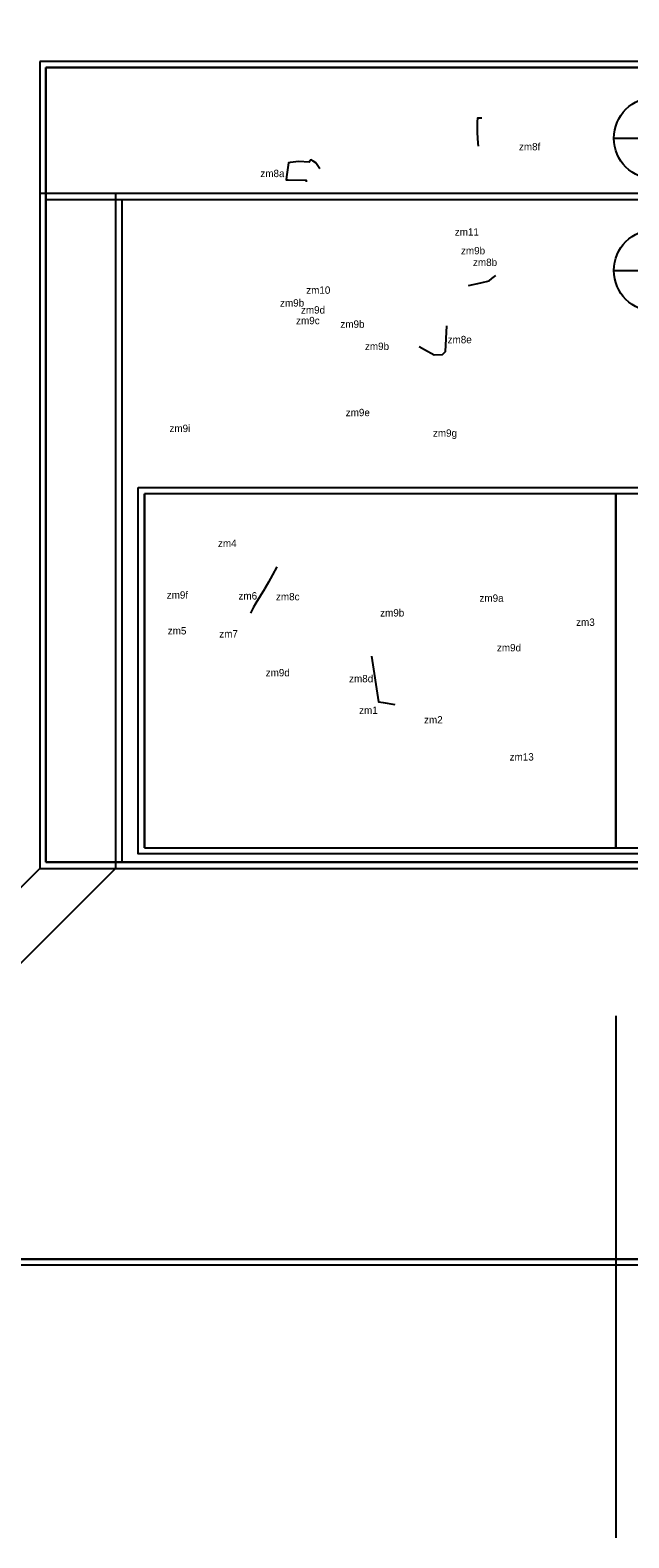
# Model space of a CAD drawing. Extents: x -557692 to -550384, y -1187532 to -1181973.
# Drawn here: x -555233 to -553772, y -1187532 to -1183851 of the extents above; entities that cross this region are included whole.
import ezdxf

# ---------------------------------------------------------------- set-up
doc = ezdxf.new("R2010")
doc.units = 0
for name, color, linetype in [('ID_zmeny', 7, 'Continuous'), ('LEG_prac_vykres_ZPF', 7, 'Continuous'), ('ram_HLV', 7, 'Continuous'), ('ram_KOO', 7, 'Continuous'), ('RAM_prac_ZPF', 7, 'Continuous'), ('ram_VPS', 7, 'Continuous'), ('ram_ZCU', 7, 'Continuous'), ('ram_ZPF', 7, 'Continuous'), ('ZU_aktualizace', 7, 'Continuous')]:
    doc.layers.add(name, color=color, linetype=linetype)

msp = doc.modelspace()

# ---------------------------------------------------------------- linework, layer by layer
at = {"layer": 'LEG_prac_vykres_ZPF'}
msp.add_lwpolyline([(-553803.9, -1186257.2), (-553803.9, -1187121.5), (-553803.9, -1187531.8)], dxfattribs=at)
at = {"layer": 'ram_HLV'}
msp.add_line((-551888.5, -1186851.2), (-555658.5, -1186851.2), dxfattribs=at)
msp.add_lwpolyline([(-555673.5, -1182466.2), (-551873.5, -1182466.2), (-551873.5, -1186866.2), (-555673.5, -1186866.2)], close=True, dxfattribs=at)
at = {"layer": 'ram_KOO'}
msp.add_line((-555658.5, -1186851.2), (-550892.3, -1186851.2), dxfattribs=at)
msp.add_lwpolyline([(-555673.5, -1182466.2), (-550877.3, -1182466.2), (-550877.3, -1186866.2), (-555673.5, -1186866.2)], close=True, dxfattribs=at)
at = {"layer": 'RAM_prac_ZPF'}
for p, q in [((-554954.4, -1185846.8), (-554954.4, -1184982.5)), ((-552518.9, -1184982.5), (-554954.4, -1184982.5)), ((-554954.4, -1184982.5), (-554954.4, -1185846.8)), ((-553803.9, -1184982.5), (-554954.4, -1184982.5)), ((-553803.9, -1184982.5), (-553803.9, -1185846.8)), ((-553803.9, -1185846.8), (-553803.9, -1184982.5)), ((-554954.4, -1185846.8), (-552518.9, -1185846.8)), ((-554954.4, -1185846.8), (-553803.9, -1185846.8))]:
    msp.add_line(p, q, dxfattribs=at)
msp.add_lwpolyline([(-554969.4, -1184967.5), (-552503.9, -1184967.5), (-552503.9, -1185861.8), (-554969.4, -1185861.8)], close=True, dxfattribs=at)
at = {"layer": 'ram_VPS'}
for p, q in [((-552520.8, -1184249.8), (-555209.8, -1184249.8)), ((-555209.8, -1184249.8), (-555209.8, -1185897.3)), ((-552520.8, -1184249.8), (-555209.8, -1184249.8)), ((-555209.8, -1184249.8), (-555209.8, -1185897.3)), ((-553535.8, -1184264.8), (-555194.8, -1184264.8)), ((-555194.8, -1184264.8), (-555194.8, -1185882.3)), ((-553808.4, -1184437.4), (-553608.4, -1184437.4)), ((-553808.4, -1184437.4), (-553608.4, -1184437.4)), ((-552535.8, -1185882.3), (-555194.8, -1185882.3)), ((-555194.8, -1185882.3), (-553535.8, -1185882.3)), ((-552535.8, -1185882.3), (-555194.8, -1185882.3)), ((-555209.8, -1185897.3), (-555704.2, -1186391.7)), ((-555209.8, -1185897.3), (-555704.2, -1186391.7)), ((-555209.8, -1185897.3), (-552520.8, -1185897.3)), ((-555209.8, -1185897.3), (-552520.8, -1185897.3))]:
    msp.add_line(p, q, dxfattribs=at)
msp.add_ellipse((-553708.4, -1184437.4), major_axis=(100, 0), ratio=0.99999, dxfattribs=at)
msp.add_ellipse((-553708.4, -1184437.4), major_axis=(100, 0), ratio=0.99999, dxfattribs=at)
at = {"layer": 'ram_ZCU'}
for p, q in [((-552520.8, -1183927), (-555209.8, -1183927)), ((-555209.8, -1183927), (-555209.8, -1185897.3)), ((-552520.8, -1183927), (-555209.8, -1183927)), ((-555209.8, -1183927), (-555209.8, -1185897.3)), ((-555194.8, -1185882.3), (-555194.8, -1183942)), ((-555194.8, -1183942), (-552535.8, -1183942)), ((-555194.8, -1183942), (-555194.8, -1185882.3)), ((-553535.8, -1183942), (-555194.8, -1183942)), ((-553808.4, -1184114.6), (-553608.4, -1184114.6)), ((-552535.8, -1185882.3), (-555194.8, -1185882.3)), ((-555194.8, -1185882.3), (-553535.8, -1185882.3)), ((-555209.8, -1185897.3), (-555704.2, -1186391.7)), ((-555209.8, -1185897.3), (-552520.8, -1185897.3)), ((-555209.8, -1185897.3), (-552520.8, -1185897.3))]:
    msp.add_line(p, q, dxfattribs=at)
msp.add_ellipse((-553708.4, -1184114.6), major_axis=(100, 0), ratio=0.99999, dxfattribs=at)
at = {"layer": 'ram_ZPF'}
for p, q in [((-551520.8, -1184249.8), (-555024.5, -1184249.8)), ((-555024.5, -1184249.8), (-555024.5, -1185897.3)), ((-553535.8, -1184264.8), (-555009.5, -1184264.8)), ((-555009.5, -1184264.8), (-555009.5, -1185882.3)), ((-553808.4, -1184437.4), (-553608.4, -1184437.4)), ((-553808.4, -1184437.4), (-553608.4, -1184437.4)), ((-555009.5, -1185882.3), (-553535.8, -1185882.3)), ((-555024.5, -1185897.3), (-555518.9, -1186391.7)), ((-555024.5, -1185897.3), (-551520.8, -1185897.3))]:
    msp.add_line(p, q, dxfattribs=at)
msp.add_ellipse((-553708.4, -1184437.4), major_axis=(100, 0), ratio=0.99999, dxfattribs=at)
msp.add_ellipse((-553708.4, -1184437.4), major_axis=(100, 0), ratio=0.99999, dxfattribs=at)
at = {"layer": 'ZU_aktualizace'}
for points in [[(-554130.8, -1184065.3), (-554141.8, -1184065.3), (-554142, -1184074.4), (-554142.2, -1184087.6), (-554142.3, -1184099.8), (-554142.3, -1184101), (-554140.5, -1184127), (-554140, -1184133.7)], [(-554525.8, -1184189.3), (-554529.4, -1184184), (-554532.8, -1184179.3), (-554536.1, -1184174.5), (-554542.4, -1184170.4), (-554547.8, -1184167.2), (-554550.3, -1184170.9), (-554551.9, -1184173.2), (-554577.5, -1184171.2), (-554598.3, -1184173.9), (-554603, -1184174.5), (-554607.4, -1184209), (-554608.3, -1184215.8), (-554603.8, -1184216.1), (-554559.9, -1184216.7), (-554559.9, -1184220.8)], [(-554163.2, -1184474.1), (-554133, -1184467.8), (-554113.2, -1184462.4), (-554106.2, -1184456.9), (-554096.8, -1184449.9)], [(-554283.8, -1184623.2), (-554271.1, -1184630.2), (-554247.5, -1184643.4), (-554227, -1184642.4), (-554219.5, -1184635.3), (-554216.1, -1184572.7)], [(-554631, -1185161), (-554641.9, -1185180.8), (-554651.5, -1185198.3)], [(-554651.5, -1185198.3), (-554660, -1185213.8), (-554661.3, -1185215.8), (-554671.9, -1185232.9), (-554682.4, -1185250), (-554688.4, -1185259.7), (-554691.9, -1185267.5), (-554695, -1185274.2)], [(-554399.9, -1185378.8), (-554383.3, -1185490.6), (-554371.7, -1185492.5), (-554343.1, -1185497.2)]]:
    msp.add_lwpolyline(points, dxfattribs=at)

# ---------------------------------------------------------------- texts
at = {"layer": 'ID_zmeny'}
for s, p in [('zm8f', (-554040.3, -1184144.2)), ('zm8a', (-554671.3, -1184209.5)), ('zm11', (-554196.8, -1184352.3)), ('zm9b', (-554181.7, -1184398)), ('zm8b', (-554152.4, -1184426.5)), ('zm10', (-554559.4, -1184494.4)), ('zm9b', (-554623.3, -1184525.6)), ('zm9d', (-554572.2, -1184542.7)), ('zm9c', (-554584.1, -1184568.7)), ('zm9b', (-554476, -1184577.4)), ('zm8e', (-554214.3, -1184615.1)), ('zm9b', (-554416.1, -1184631.6)), ('zm9e', (-554462.9, -1184793.2)), ('zm9i', (-554893.2, -1184832)), ('zm9g', (-554250.2, -1184843.4)), ('zm4', (-554774.7, -1185112.4)), ('zm9f', (-554899.8, -1185238.7)), ('zm6', (-554724.7, -1185240.9)), ('zm8c', (-554633.2, -1185242.8)), ('zm9b', (-554379, -1185282.3)), ('zm9a', (-554136.6, -1185246.4)), ('zm3', (-553900.8, -1185305.2)), ('zm5', (-554897.3, -1185326.1)), ('zm7', (-554771.6, -1185333.6)), ('zm9d', (-554094, -1185367.5)), ('zm9d', (-554658.3, -1185428.5)), ('zm8d', (-554454.8, -1185443)), ('zm1', (-554430.3, -1185520.2)), ('zm2', (-554271.9, -1185543.5)), ('zm13', (-554063, -1185634))]:
    msp.add_text(s, height=18, dxfattribs=at).set_placement(p)

doc.saveas('drawing.dxf')
